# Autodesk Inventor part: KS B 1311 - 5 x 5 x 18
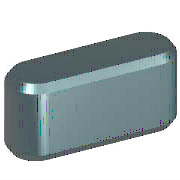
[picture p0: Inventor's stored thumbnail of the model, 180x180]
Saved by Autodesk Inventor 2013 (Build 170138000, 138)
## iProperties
IsCustomPart: 0
Created: 2009-02
Part Number: KS B 1311 - 5 x 5 x 18
Material: 강, 연강
Description: 키 및 해당 키홈
Document SubType Name: Modeling
Standard: KS B 1311
Designer: KYOUNG IL JANG
Standards Organization: KS
Language: ko-KR
Size Designation: 5 x 5 x 18
Categories: <MemberInstance><Categories><Category DisplayName="샤프트 부품" InternalName="7f7aeb1f-a693-4053-b835-cee3144e0d98" Mnemonic="SHFT"><Category DisplayName="키" Interna
Density: 7.86 g/cm^3
Mass: 3.27476 g
Surface Area: 3.57848 cm^2
Volume: 0.416636 cm^3
Author: KYOUNG IL JANG
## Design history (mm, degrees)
workplane "Work Plane1"
workplane "Work Plane2"
sketch "스케치1"
  geometry: L1 (2.5, 2.5)-(15.5, 2.5); L2 (15.5, -2.5)-(2.5, -2.5); L3 (0, 9.4)-(0, -7.4) reference; L4 (-5, 0)-(30, 0) reference; L5 (18, 0)-(18, 7); A1 r 2.5 centre (2.5, 0) between (2.5, 2.5) and (2.5, -2.5); A2 r 2.5 centre (15.5, 0) between (15.5, -2.5) and (15.5, 2.5)
  constraints: 6 end point, 5 point on circle, 4 tangent, 3 point on line, 2 centre point, 1 horizontal, 1 parallel, 1 perpendicular
  dimensions: "d0" = 2.5 radius of A1 (= 0.5 x PB); "d13" = 2.5 radius of A2 (= 0.5 x PB); "d14" = 18 distance between parallel lines of L5 L3 (= NLG)
extrude "본체1" new body sketch "스케치1" taper "d3" = 0 deg; stored distance "d4" = 10
workplane "Work Plane3"
body "Solid1"
chamfer "모따기1" distance "d8" = 0.4 (= PHH); stored, may be unused: second distance "d9" = 0.4 (= PHH), angle "d15" = 45 deg
other parameters: "d1" = -3 (= -PNT), "d2" = 2 (= PH - PNT), "NLG" = 18 [user parameter; used in 3 equation terms], "PB" = 5 [user parameter; used in 2 equation terms], "PNT" = 3 [user parameter; used in 2 equation terms], "PH" = 5 [user parameter; used in 1 equation term], "PHH" = 0.4 [user parameter; used in 2 equation terms], "d10" = 0, "d16" = 0, "d17" = 0, "d18" = 0, "WDMIN" = 12 [user parameter], "PLB2" = 18 (= NLG) [user parameter], "WDMAX" = 17 [user parameter], "PLB1" = 18 (= NLG) [user parameter], "RR" = 0.16 [user parameter], "PUEB" = 2.3 [user parameter]
